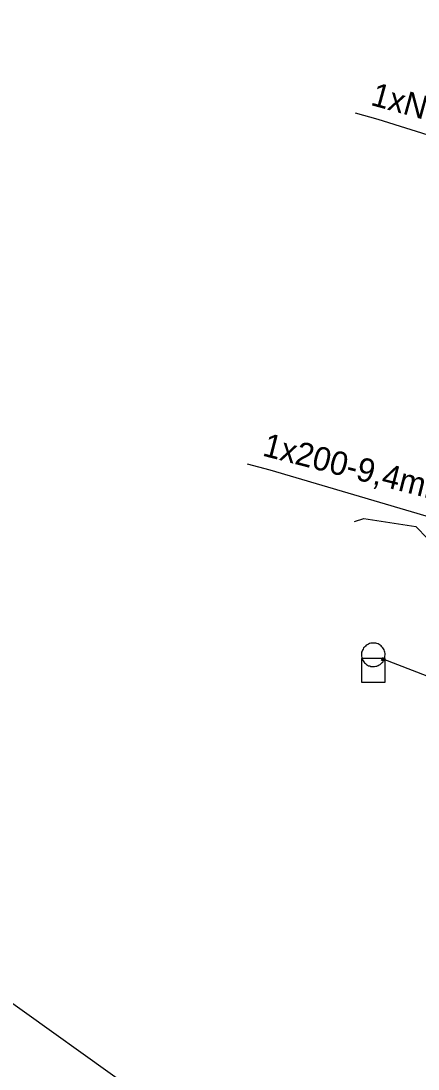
# Model space of a CAD drawing. Extents: x -746464 to -745690, y -1051581 to -1049993.
# Drawn here: x -746121.38 to -746104.52, y -1050681.08 to -1050636.55 of the extents above; entities that cross this region are included whole.
import ezdxf

# ---------------------------------------------------------------- set-up
doc = ezdxf.new("R2010")
doc.units = 0
for name, color, linetype in [('04_CETIN_radiove site', 7, 'Continuous'), ('04_CETIN_sdelovaci_podzem', 7, 'Continuous'), ('51_PVaK_vodovod_chranicky_objekty', 7, 'Continuous'), ('51_PVaK_vodovod_NEPROVOZUJE PVK_overena poloha', 7, 'Continuous'), ('55_PREdi_stavby_popisy', 7, 'Continuous')]:
    doc.layers.add(name, color=color, linetype=linetype)

msp = doc.modelspace()

# ---------------------------------------------------------------- linework, layer by layer
at = {"layer": '04_CETIN_radiove site'}
msp.add_line((-745690.053, -1050986.801), (-746458.107, -1050437.909), dxfattribs=at)
at = {"layer": '04_CETIN_sdelovaci_podzem'}
msp.add_lwpolyline([(-746107.22, -1050657.82), (-746106.82, -1050657.69), (-746104.62, -1050658.02), (-746103.63, -1050659.04), (-746098.83, -1050660.48), (-746097.21, -1050660.93), (-746096.68, -1050660.58)], dxfattribs=at)
msp.add_lwpolyline([(-746107.22, -1050657.82), (-746106.82, -1050657.69), (-746104.62, -1050658.02), (-746103.63, -1050659.04), (-746098.83, -1050660.48), (-746097.21, -1050660.93), (-746096.68, -1050660.58)], dxfattribs=at)
at = {"layer": '51_PVaK_vodovod_chranicky_objekty'}
for p, q in [((-746106.071, -1050663.703), (-746105.947, -1050663.636)), ((-746106.071, -1050663.703), (-746106.065, -1050663.684)), ((-746106.071, -1050663.703), (-746106.052, -1050663.709)), ((-746106.042, -1050663.607), (-746106.048, -1050663.626)), ((-746106.042, -1050663.607), (-746105.975, -1050663.731)), ((-746106.042, -1050663.607), (-746106.023, -1050663.613)), ((-746105.975, -1050663.731), (-746105.994, -1050663.726)), ((-746105.975, -1050663.731), (-746105.969, -1050663.712)), ((-746105.947, -1050663.636), (-746105.966, -1050663.63)), ((-746105.947, -1050663.636), (-746105.952, -1050663.655))]:
    msp.add_line(p, q, dxfattribs=at)
for points in [[(-746106.888, -1050663.276), (-746106.899, -1050663.327), (-746106.919, -1050663.373), (-746106.92, -1050663.428), (-746106.922, -1050663.482), (-746106.924, -1050663.537), (-746106.912, -1050663.586), (-746106.9, -1050663.635), (-746106.88, -1050663.688), (-746106.855, -1050663.732), (-746106.83, -1050663.776), (-746106.791, -1050663.815), (-746106.753, -1050663.854), (-746106.715, -1050663.893), (-746106.668, -1050663.913), (-746106.626, -1050663.942), (-746106.576, -1050663.953), (-746106.529, -1050663.974), (-746106.475, -1050663.975), (-746106.42, -1050663.977), (-746106.366, -1050663.979), (-746106.317, -1050663.967), (-746106.267, -1050663.955), (-746106.214, -1050663.934), (-746106.17, -1050663.909), (-746106.126, -1050663.884), (-746106.087, -1050663.846), (-746106.048, -1050663.808), (-746106.01, -1050663.77), (-746105.989, -1050663.723), (-746105.96, -1050663.681), (-746105.949, -1050663.63), (-746105.929, -1050663.584), (-746105.927, -1050663.529), (-746105.925, -1050663.475), (-746105.924, -1050663.421), (-746105.935, -1050663.371), (-746105.947, -1050663.322), (-746105.968, -1050663.269), (-746105.993, -1050663.225), (-746106.018, -1050663.181), (-746106.056, -1050663.142), (-746106.095, -1050663.103), (-746106.133, -1050663.064), (-746106.179, -1050663.044), (-746106.222, -1050663.015), (-746106.272, -1050663.004), (-746106.318, -1050662.984), (-746106.373, -1050662.982), (-746106.427, -1050662.98), (-746106.482, -1050662.979), (-746106.531, -1050662.99), (-746106.58, -1050663.002), (-746106.634, -1050663.023), (-746106.678, -1050663.048), (-746106.722, -1050663.073), (-746106.76, -1050663.111), (-746106.799, -1050663.149), (-746106.838, -1050663.188), (-746106.858, -1050663.234), (-746106.888, -1050663.276)], [(-746105.961, -1050663.684), (-746105.959, -1050663.679), (-746105.959, -1050663.674), (-746105.958, -1050663.669), (-746105.959, -1050663.663), (-746105.96, -1050663.658), (-746105.962, -1050663.653), (-746105.964, -1050663.648), (-746105.967, -1050663.643), (-746105.97, -1050663.639), (-746105.973, -1050663.635), (-746105.976, -1050663.631), (-746105.981, -1050663.628), (-746105.985, -1050663.625), (-746105.99, -1050663.623), (-746105.995, -1050663.621), (-746105.999, -1050663.62), (-746106.004, -1050663.62), (-746106.009, -1050663.619), (-746106.015, -1050663.62), (-746106.02, -1050663.621), (-746106.025, -1050663.623), (-746106.03, -1050663.624), (-746106.035, -1050663.627), (-746106.039, -1050663.63), (-746106.043, -1050663.633), (-746106.047, -1050663.637), (-746106.051, -1050663.641), (-746106.053, -1050663.646), (-746106.055, -1050663.65), (-746106.057, -1050663.655), (-746106.058, -1050663.66), (-746106.059, -1050663.665), (-746106.059, -1050663.67), (-746106.059, -1050663.675), (-746106.057, -1050663.681), (-746106.055, -1050663.686), (-746106.054, -1050663.69), (-746106.051, -1050663.695), (-746106.048, -1050663.699), (-746106.045, -1050663.703), (-746106.041, -1050663.708), (-746106.037, -1050663.711), (-746106.032, -1050663.713), (-746106.028, -1050663.716), (-746106.023, -1050663.717), (-746106.018, -1050663.719), (-746106.013, -1050663.719), (-746106.008, -1050663.72), (-746106.003, -1050663.719), (-746105.997, -1050663.718), (-746105.992, -1050663.716), (-746105.988, -1050663.714), (-746105.983, -1050663.711), (-746105.979, -1050663.709), (-746105.975, -1050663.706), (-746105.97, -1050663.702), (-746105.967, -1050663.697), (-746105.965, -1050663.693), (-746105.962, -1050663.688), (-746105.961, -1050663.684)]]:
    msp.add_lwpolyline(points, dxfattribs=at)
msp.add_lwpolyline([(-746106.924, -1050664.634), (-746105.924, -1050664.634), (-746105.924, -1050663.634), (-746106.924, -1050663.634)], close=True, dxfattribs=at)
at = {"layer": '51_PVaK_vodovod_NEPROVOZUJE PVK_overena poloha'}
msp.add_line((-746100.05, -1050665.96), (-746106.01, -1050663.67), dxfattribs=at)
at = {"layer": '55_PREdi_stavby_popisy'}
for points in [[(-746107.195, -1050640.458), (-746106.231, -1050640.723), (-746092.409, -1050645.055)], [(-746111.78, -1050655.367), (-746110.812, -1050655.616), (-746097.093, -1050659.671)]]:
    msp.add_lwpolyline(points, dxfattribs=at)

# ---------------------------------------------------------------- texts
for s, rotation, p in [('1xNEZ.4,1mTK2', 344.6296, (-746106.58, -1050640.109)), ('1x200-9,4mPVC', 345.5929, (-746111.172, -1050655.008))]:
    msp.add_text(s, height=1, rotation=rotation, dxfattribs=at).set_placement(p)

doc.saveas('drawing.dxf')
